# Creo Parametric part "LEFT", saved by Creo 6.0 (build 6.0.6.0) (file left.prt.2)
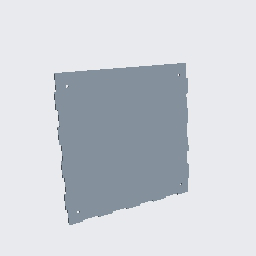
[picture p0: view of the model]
Units: Inch lbm Second (Pro/E Default); INCH, POUND, SECS

Created from: INLBS_PART_SOLID.PRT

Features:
  1. datum plane "RIGHT"
  2. datum plane "TOP"
  3. datum plane "FRONT"
  4. coordinate system
  5. sketch "Sketch 1"
  6. extrusion "Extrude 1"
  7. sketch "Sketch 2"
  8. extruded cut "Extrude 2"

Surfaces: 54 plane, 4 cylinder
